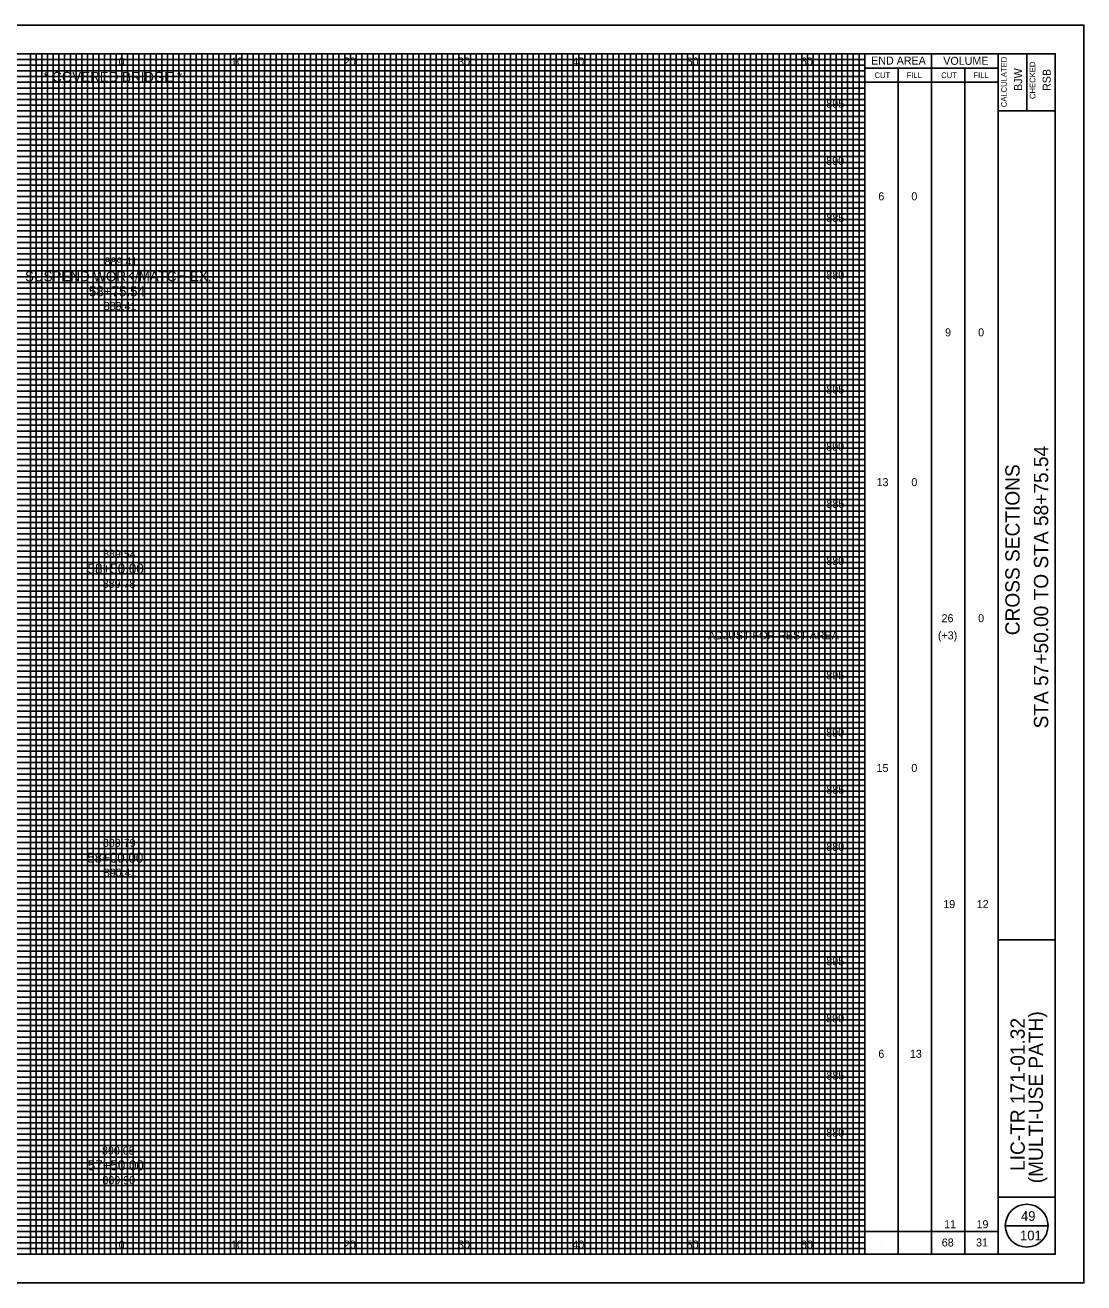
# Model space of a CAD drawing. Extents: x -10 to 160, y -2 to 2522.
# Drawn here: x 67.4 to 160, y 2412.5 to 2522.5 of the extents above; entities that cross this region are included whole.
import ezdxf

# ---------------------------------------------------------------- set-up
doc = ezdxf.new("R2010")
doc.units = 0
for name, color, linetype in [('GK_Cells', 7, 'Continuous'), ('GK_Patterns', 7, 'Continuous'), ('TX_P_10', 7, 'Continuous'), ('TX_X_10', 7, 'Continuous'), ('XS_P_Finished_Grade_Seeded', 7, 'Continuous'), ('XS_P_Pavt_Surface', 7, 'Continuous'), ('XS_P_Subgrade', 7, 'Continuous'), ('XS_X_Ground_Line', 7, 'Continuous')]:
    doc.layers.add(name, color=color, linetype=linetype)

msp = doc.modelspace()

# ---------------------------------------------------------------- linework, layer by layer
at = {"layer": 'GK_Cells'}
msp.add_lwpolyline([(-10, 2412.5), (160, 2412.5), (160, 2522.5), (-10, 2522.5)], close=True, dxfattribs=at)
at = {"layer": 'TX_P_10'}
for p, q in [((140.83, 2415), (140.83, 2520)), ((146.67, 2415), (146.67, 2520)), ((140.83, 2518.75), (152.5, 2518.75)), ((143.75, 2415), (143.75, 2518.75)), ((149.58, 2415), (149.58, 2518.75)), ((140.83, 2517.5), (152.5, 2517.5)), ((140.83, 2417), (152.5, 2417)), ((153.12, 2417.5), (156.88, 2417.5)), ((142.29, 2416), (142.29, 2416)), ((145.21, 2416), (145.21, 2416)), ((148.12, 2416), (148.12, 2416)), ((151.04, 2416), (151.04, 2416))]:
    msp.add_line(p, q, dxfattribs=at)
msp.add_circle((155, 2417.5), 1.87, dxfattribs=at)
at = {"layer": 'TX_X_10'}
for p, q in [((70.83, 2415), (70.83, 2520)), ((75.83, 2415), (75.83, 2520)), ((80.83, 2415), (80.83, 2520)), ((85.83, 2415), (85.83, 2520)), ((90.83, 2415), (90.83, 2520)), ((95.83, 2415), (95.83, 2520)), ((100.83, 2415), (100.83, 2520)), ((105.83, 2415), (105.83, 2520)), ((110.83, 2415), (110.83, 2520)), ((115.83, 2415), (115.83, 2520)), ((120.83, 2415), (120.83, 2520)), ((125.83, 2415), (125.83, 2520)), ((130.83, 2415), (130.83, 2520)), ((135.83, 2415), (135.83, 2520)), ((5.83, 2515), (140.83, 2515)), ((5.83, 2510), (140.83, 2510)), ((5.83, 2505), (140.83, 2505)), ((5.83, 2500), (140.83, 2500)), ((5.83, 2495), (140.83, 2495)), ((5.83, 2490), (140.83, 2490)), ((5.83, 2485), (140.83, 2485)), ((5.83, 2480), (140.83, 2480)), ((5.83, 2475), (140.83, 2475)), ((5.83, 2470), (140.83, 2470)), ((5.83, 2465), (140.83, 2465)), ((5.83, 2460), (140.83, 2460)), ((5.83, 2455), (140.83, 2455)), ((5.83, 2450), (140.83, 2450)), ((5.83, 2445), (140.83, 2445)), ((5.83, 2440), (140.83, 2440)), ((5.83, 2435), (140.83, 2435)), ((5.83, 2430), (140.83, 2430)), ((5.83, 2425), (140.83, 2425)), ((5.83, 2420), (140.83, 2420))]:
    msp.add_line(p, q, dxfattribs=at)
at = {"layer": 'XS_P_Pavt_Surface'}
for p, q in [((152.5, 2415), (152.5, 2520)), ((155, 2520), (155, 2515)), ((152.5, 2515), (157.5, 2515)), ((152.5, 2442.5), (157.5, 2442.5)), ((152.5, 2420), (157.5, 2420))]:
    msp.add_line(p, q, dxfattribs=at)
msp.add_lwpolyline([(0, 2520), (157.5, 2520), (157.5, 2415), (0, 2415)], close=True, dxfattribs=at)
at = {"layer": 'XS_X_Ground_Line'}
for p, q in [((5.83, 2519.5), (140.83, 2519.5)), ((5.83, 2519), (140.83, 2519)), ((67.83, 2415), (67.83, 2520)), ((68.33, 2415), (68.33, 2520)), ((68.83, 2415), (68.83, 2520)), ((69.33, 2415), (69.33, 2520)), ((69.83, 2415), (69.83, 2520)), ((70.33, 2415), (70.33, 2520)), ((71.33, 2415), (71.33, 2520)), ((71.83, 2415), (71.83, 2520)), ((72.33, 2415), (72.33, 2520)), ((72.83, 2415), (72.83, 2520)), ((73.33, 2415), (73.33, 2520)), ((73.83, 2415), (73.83, 2520)), ((74.33, 2415), (74.33, 2520)), ((74.83, 2415), (74.83, 2520)), ((75.33, 2415), (75.33, 2520)), ((76.33, 2415), (76.33, 2520)), ((76.83, 2415), (76.83, 2520)), ((77.33, 2415), (77.33, 2520)), ((77.83, 2415), (77.83, 2520)), ((78.33, 2415), (78.33, 2520)), ((78.83, 2415), (78.83, 2520)), ((79.33, 2415), (79.33, 2520)), ((79.83, 2415), (79.83, 2520)), ((80.33, 2415), (80.33, 2520)), ((81.33, 2415), (81.33, 2520)), ((81.83, 2415), (81.83, 2520)), ((82.33, 2415), (82.33, 2520)), ((82.83, 2415), (82.83, 2520)), ((83.33, 2415), (83.33, 2520)), ((83.83, 2415), (83.83, 2520)), ((84.33, 2415), (84.33, 2520)), ((84.83, 2415), (84.83, 2520)), ((85.33, 2415), (85.33, 2520)), ((86.33, 2415), (86.33, 2520)), ((86.83, 2415), (86.83, 2520)), ((87.33, 2415), (87.33, 2520)), ((87.83, 2415), (87.83, 2520)), ((88.33, 2415), (88.33, 2520)), ((88.83, 2415), (88.83, 2520)), ((89.33, 2415), (89.33, 2520)), ((89.83, 2415), (89.83, 2520)), ((90.33, 2415), (90.33, 2520)), ((91.33, 2415), (91.33, 2520)), ((91.83, 2415), (91.83, 2520)), ((92.33, 2415), (92.33, 2520)), ((92.83, 2415), (92.83, 2520)), ((93.33, 2415), (93.33, 2520)), ((93.83, 2415), (93.83, 2520)), ((94.33, 2415), (94.33, 2520)), ((94.83, 2415), (94.83, 2520)), ((95.33, 2415), (95.33, 2520)), ((96.33, 2415), (96.33, 2520)), ((96.83, 2415), (96.83, 2520)), ((97.33, 2415), (97.33, 2520)), ((97.83, 2415), (97.83, 2520)), ((98.33, 2415), (98.33, 2520)), ((98.83, 2415), (98.83, 2520)), ((99.33, 2415), (99.33, 2520)), ((99.83, 2415), (99.83, 2520)), ((100.33, 2415), (100.33, 2520)), ((101.33, 2415), (101.33, 2520)), ((101.83, 2415), (101.83, 2520)), ((102.33, 2415), (102.33, 2520)), ((102.83, 2415), (102.83, 2520)), ((103.33, 2415), (103.33, 2520)), ((103.83, 2415), (103.83, 2520)), ((104.33, 2415), (104.33, 2520)), ((104.83, 2415), (104.83, 2520)), ((105.33, 2415), (105.33, 2520)), ((106.33, 2415), (106.33, 2520)), ((106.83, 2415), (106.83, 2520)), ((107.33, 2415), (107.33, 2520)), ((107.83, 2415), (107.83, 2520)), ((108.33, 2415), (108.33, 2520)), ((108.83, 2415), (108.83, 2520)), ((109.33, 2415), (109.33, 2520)), ((109.83, 2415), (109.83, 2520)), ((110.33, 2415), (110.33, 2520)), ((111.33, 2415), (111.33, 2520)), ((111.83, 2415), (111.83, 2520)), ((112.33, 2415), (112.33, 2520)), ((112.83, 2415), (112.83, 2520)), ((113.33, 2415), (113.33, 2520)), ((113.83, 2415), (113.83, 2520)), ((114.33, 2415), (114.33, 2520)), ((114.83, 2415), (114.83, 2520)), ((115.33, 2415), (115.33, 2520)), ((116.33, 2415), (116.33, 2520)), ((116.83, 2415), (116.83, 2520)), ((117.33, 2415), (117.33, 2520)), ((117.83, 2415), (117.83, 2520)), ((118.33, 2415), (118.33, 2520)), ((118.83, 2415), (118.83, 2520)), ((119.33, 2415), (119.33, 2520)), ((119.83, 2415), (119.83, 2520)), ((120.33, 2415), (120.33, 2520)), ((121.33, 2415), (121.33, 2520)), ((121.83, 2415), (121.83, 2520)), ((122.33, 2415), (122.33, 2520)), ((122.83, 2415), (122.83, 2520)), ((123.33, 2415), (123.33, 2520)), ((123.83, 2415), (123.83, 2520)), ((124.33, 2415), (124.33, 2520)), ((124.83, 2415), (124.83, 2520)), ((125.33, 2415), (125.33, 2520)), ((126.33, 2415), (126.33, 2520)), ((126.83, 2415), (126.83, 2520)), ((127.33, 2415), (127.33, 2520)), ((127.83, 2415), (127.83, 2520)), ((128.33, 2415), (128.33, 2520)), ((128.83, 2415), (128.83, 2520)), ((129.33, 2415), (129.33, 2520)), ((129.83, 2415), (129.83, 2520)), ((130.33, 2415), (130.33, 2520)), ((131.33, 2415), (131.33, 2520)), ((131.83, 2415), (131.83, 2520)), ((132.33, 2415), (132.33, 2520)), ((132.83, 2415), (132.83, 2520)), ((133.33, 2415), (133.33, 2520)), ((133.83, 2415), (133.83, 2520)), ((134.33, 2415), (134.33, 2520)), ((134.83, 2415), (134.83, 2520)), ((135.33, 2415), (135.33, 2520)), ((136.33, 2415), (136.33, 2520)), ((136.83, 2415), (136.83, 2520)), ((137.33, 2415), (137.33, 2520)), ((137.83, 2415), (137.83, 2520)), ((138.33, 2415), (138.33, 2520)), ((138.83, 2415), (138.83, 2520)), ((139.33, 2415), (139.33, 2520)), ((139.83, 2415), (139.83, 2520)), ((140.33, 2415), (140.33, 2520)), ((5.83, 2518.5), (140.83, 2518.5)), ((5.83, 2518), (140.83, 2518)), ((5.83, 2517.5), (140.83, 2517.5)), ((5.83, 2517), (140.83, 2517)), ((5.83, 2516.5), (140.83, 2516.5)), ((5.83, 2516), (140.83, 2516)), ((5.83, 2515.5), (140.83, 2515.5)), ((5.83, 2514.5), (140.83, 2514.5)), ((5.83, 2514), (140.83, 2514)), ((5.83, 2513.5), (140.83, 2513.5)), ((5.83, 2513), (140.83, 2513)), ((5.83, 2512.5), (140.83, 2512.5)), ((5.83, 2512), (140.83, 2512)), ((5.83, 2511.5), (140.83, 2511.5)), ((5.83, 2511), (140.83, 2511)), ((5.83, 2510.5), (140.83, 2510.5)), ((5.83, 2509.5), (140.83, 2509.5)), ((5.83, 2509), (140.83, 2509)), ((5.83, 2508.5), (140.83, 2508.5)), ((5.83, 2508), (140.83, 2508)), ((5.83, 2507.5), (140.83, 2507.5)), ((5.83, 2507), (140.83, 2507)), ((5.83, 2506.5), (140.83, 2506.5)), ((5.83, 2506), (140.83, 2506)), ((5.83, 2505.5), (140.83, 2505.5)), ((5.83, 2504.5), (140.83, 2504.5)), ((5.83, 2504), (140.83, 2504)), ((5.83, 2503.5), (140.83, 2503.5)), ((5.83, 2503), (140.83, 2503)), ((5.83, 2502.5), (140.83, 2502.5)), ((5.83, 2502), (140.83, 2502)), ((5.83, 2501.5), (140.83, 2501.5)), ((5.83, 2501), (140.83, 2501)), ((5.83, 2500.5), (140.83, 2500.5)), ((5.83, 2499.5), (140.83, 2499.5)), ((5.83, 2499), (140.83, 2499)), ((5.83, 2498.5), (140.83, 2498.5)), ((5.83, 2498), (140.83, 2498)), ((5.83, 2497.5), (140.83, 2497.5)), ((5.83, 2497), (140.83, 2497)), ((5.83, 2496.5), (140.83, 2496.5)), ((5.83, 2496), (140.83, 2496)), ((5.83, 2495.5), (140.83, 2495.5)), ((5.83, 2494.5), (140.83, 2494.5)), ((5.83, 2494), (140.83, 2494)), ((5.83, 2493.5), (140.83, 2493.5)), ((5.83, 2493), (140.83, 2493)), ((5.83, 2492.5), (140.83, 2492.5)), ((5.83, 2492), (140.83, 2492)), ((5.83, 2491.5), (140.83, 2491.5)), ((5.83, 2491), (140.83, 2491)), ((5.83, 2490.5), (140.83, 2490.5)), ((5.83, 2489.5), (140.83, 2489.5)), ((5.83, 2489), (140.83, 2489)), ((5.83, 2488.5), (140.83, 2488.5)), ((5.83, 2488), (140.83, 2488)), ((5.83, 2487.5), (140.83, 2487.5)), ((5.83, 2487), (140.83, 2487)), ((5.83, 2486.5), (140.83, 2486.5)), ((5.83, 2486), (140.83, 2486)), ((5.83, 2485.5), (140.83, 2485.5)), ((5.83, 2484.5), (140.83, 2484.5)), ((5.83, 2484), (140.83, 2484)), ((5.83, 2483.5), (140.83, 2483.5)), ((5.83, 2483), (140.83, 2483)), ((5.83, 2482.5), (140.83, 2482.5)), ((5.83, 2482), (140.83, 2482)), ((5.83, 2481.5), (140.83, 2481.5)), ((5.83, 2481), (140.83, 2481)), ((5.83, 2480.5), (140.83, 2480.5)), ((5.83, 2479.5), (140.83, 2479.5)), ((5.83, 2479), (140.83, 2479)), ((5.83, 2478.5), (140.83, 2478.5)), ((5.83, 2478), (140.83, 2478)), ((5.83, 2477.5), (140.83, 2477.5)), ((5.83, 2477), (140.83, 2477)), ((5.83, 2476.5), (140.83, 2476.5)), ((5.83, 2476), (140.83, 2476)), ((5.83, 2475.5), (140.83, 2475.5)), ((5.83, 2474.5), (140.83, 2474.5)), ((5.83, 2474), (140.83, 2474)), ((5.83, 2473.5), (140.83, 2473.5)), ((5.83, 2473), (140.83, 2473)), ((5.83, 2472.5), (140.83, 2472.5)), ((5.83, 2472), (140.83, 2472)), ((5.83, 2471.5), (140.83, 2471.5)), ((5.83, 2471), (140.83, 2471)), ((5.83, 2470.5), (140.83, 2470.5)), ((5.83, 2469.5), (140.83, 2469.5)), ((5.83, 2469), (140.83, 2469)), ((5.83, 2468.5), (140.83, 2468.5)), ((5.83, 2468), (140.83, 2468)), ((5.83, 2467.5), (140.83, 2467.5)), ((5.83, 2467), (140.83, 2467)), ((5.83, 2466.5), (140.83, 2466.5)), ((5.83, 2466), (140.83, 2466)), ((5.83, 2465.5), (140.83, 2465.5)), ((5.83, 2464.5), (140.83, 2464.5)), ((5.83, 2464), (140.83, 2464)), ((5.83, 2463.5), (140.83, 2463.5)), ((5.83, 2463), (140.83, 2463)), ((5.83, 2462.5), (140.83, 2462.5)), ((5.83, 2462), (140.83, 2462)), ((5.83, 2461.5), (140.83, 2461.5)), ((5.83, 2461), (140.83, 2461)), ((5.83, 2460.5), (140.83, 2460.5)), ((5.83, 2459.5), (140.83, 2459.5)), ((5.83, 2459), (140.83, 2459)), ((5.83, 2458.5), (140.83, 2458.5)), ((5.83, 2458), (140.83, 2458)), ((5.83, 2457.5), (140.83, 2457.5)), ((5.83, 2457), (140.83, 2457)), ((5.83, 2456.5), (140.83, 2456.5)), ((5.83, 2456), (140.83, 2456)), ((5.83, 2455.5), (140.83, 2455.5)), ((5.83, 2454.5), (140.83, 2454.5)), ((5.83, 2454), (140.83, 2454)), ((5.83, 2453.5), (140.83, 2453.5)), ((5.83, 2453), (140.83, 2453)), ((5.83, 2452.5), (140.83, 2452.5)), ((5.83, 2452), (140.83, 2452)), ((5.83, 2451.5), (140.83, 2451.5)), ((5.83, 2451), (140.83, 2451)), ((5.83, 2450.5), (140.83, 2450.5)), ((5.83, 2449.5), (140.83, 2449.5)), ((5.83, 2449), (140.83, 2449)), ((5.83, 2448.5), (140.83, 2448.5)), ((5.83, 2448), (140.83, 2448)), ((5.83, 2447.5), (140.83, 2447.5)), ((5.83, 2447), (140.83, 2447)), ((5.83, 2446.5), (140.83, 2446.5)), ((5.83, 2446), (140.83, 2446)), ((5.83, 2445.5), (140.83, 2445.5)), ((5.83, 2444.5), (140.83, 2444.5)), ((5.83, 2444), (140.83, 2444)), ((5.83, 2443.5), (140.83, 2443.5)), ((5.83, 2443), (140.83, 2443)), ((5.83, 2442.5), (140.83, 2442.5)), ((5.83, 2442), (140.83, 2442)), ((5.83, 2441.5), (140.83, 2441.5)), ((5.83, 2441), (140.83, 2441)), ((5.83, 2440.5), (140.83, 2440.5)), ((5.83, 2439.5), (140.83, 2439.5)), ((5.83, 2439), (140.83, 2439)), ((5.83, 2438.5), (140.83, 2438.5)), ((5.83, 2438), (140.83, 2438)), ((5.83, 2437.5), (140.83, 2437.5)), ((5.83, 2437), (140.83, 2437)), ((5.83, 2436.5), (140.83, 2436.5)), ((5.83, 2436), (140.83, 2436)), ((5.83, 2435.5), (140.83, 2435.5)), ((5.83, 2434.5), (140.83, 2434.5)), ((5.83, 2434), (140.83, 2434)), ((5.83, 2433.5), (140.83, 2433.5)), ((5.83, 2433), (140.83, 2433)), ((5.83, 2432.5), (140.83, 2432.5)), ((5.83, 2432), (140.83, 2432)), ((5.83, 2431.5), (140.83, 2431.5)), ((5.83, 2431), (140.83, 2431)), ((5.83, 2430.5), (140.83, 2430.5)), ((5.83, 2429.5), (140.83, 2429.5)), ((5.83, 2429), (140.83, 2429)), ((5.83, 2428.5), (140.83, 2428.5)), ((5.83, 2428), (140.83, 2428)), ((5.83, 2427.5), (140.83, 2427.5)), ((5.83, 2427), (140.83, 2427)), ((5.83, 2426.5), (140.83, 2426.5)), ((5.83, 2426), (140.83, 2426)), ((5.83, 2425.5), (140.83, 2425.5)), ((5.83, 2424.5), (140.83, 2424.5)), ((5.83, 2424), (140.83, 2424)), ((5.83, 2423.5), (140.83, 2423.5)), ((5.83, 2423), (140.83, 2423)), ((5.83, 2422.5), (140.83, 2422.5)), ((5.83, 2422), (140.83, 2422)), ((5.83, 2421.5), (140.83, 2421.5)), ((5.83, 2421), (140.83, 2421)), ((5.83, 2420.5), (140.83, 2420.5)), ((5.83, 2419.5), (140.83, 2419.5)), ((5.83, 2419), (140.83, 2419)), ((5.83, 2418.5), (140.83, 2418.5)), ((5.83, 2418), (140.83, 2418)), ((5.83, 2417.5), (140.83, 2417.5)), ((5.83, 2417), (140.83, 2417)), ((5.83, 2416.5), (140.83, 2416.5)), ((5.83, 2416), (140.83, 2416)), ((5.83, 2415.5), (140.83, 2415.5))]:
    msp.add_line(p, q, dxfattribs=at)

# ---------------------------------------------------------------- texts
at = {"layer": 'GK_Patterns'}
for s, height, p in [('0', 0.7, (75.55, 2518.97)), ('0', 0.7, (75.55, 2518.97)), ('10', 0.7, (85.39, 2518.97)), ('20', 0.7, (95.26, 2518.97)), ('30', 0.7, (105.25, 2518.97)), ('40', 0.7, (115.25, 2518.97)), ('50', 0.7, (125.25, 2518.97)), ('60', 0.7, (135.25, 2518.97)), ('* COVERED BRIDGE *', 0.875, (68.96, 2517.54)), ('895', 0.7, (137.47, 2515.28)), ('890', 0.7, (137.46, 2510.28)), ('6', 0.7, (142.02, 2507.18)), ('0', 0.7, (144.91, 2507.18)), ('885', 0.7, (137.48, 2505.28)), ('SUSPEND WORK/MATCH EX.', 0.875, (67.36, 2500.1)), ('880', 0.7, (137.47, 2500.28)), ('58+75.54', 0.875, (72.95, 2498.79)), ('9', 0.7, (147.86, 2495.28)), ('0', 0.7, (150.75, 2495.28)), ('895', 0.7, (137.47, 2490.28)), ('890', 0.7, (137.46, 2485.28)), ('13', 0.7, (141.87, 2482.18)), ('0', 0.7, (144.91, 2482.18)), ('885', 0.7, (137.48, 2480.28)), ('58+50.00', 0.875, (72.84, 2474.53)), ('880', 0.7, (137.47, 2475.28)), ('26', 0.7, (147.55, 2470.28)), ('0', 0.7, (150.75, 2470.28)), ('(+3)', 0.7, (147.23, 2468.78)), ('ADJUST FOR REST AREA', 0.7, (127.12, 2468.78)), ('895', 0.7, (137.47, 2465.28)), ('890', 0.7, (137.46, 2460.28)), ('15', 0.7, (141.86, 2457.18)), ('0', 0.7, (144.91, 2457.18)), ('885', 0.7, (137.48, 2455.28)), ('880', 0.7, (137.47, 2450.28)), ('58+00.00', 0.875, (72.8, 2449.25)), ('19', 0.7, (147.7, 2445.28)), ('12', 0.7, (150.63, 2445.28)), ('895', 0.7, (137.47, 2440.28)), ('890', 0.7, (137.46, 2435.28)), ('6', 0.7, (142.02, 2432.18)), ('13', 0.7, (144.78, 2432.18)), ('885', 0.7, (137.48, 2430.28)), ('880', 0.7, (137.47, 2425.28)), ('57+50.00', 0.875, (72.85, 2422.34)), ('11', 0.7, (147.78, 2417.28)), ('19', 0.7, (150.61, 2417.28)), ('0', 0.7, (75.55, 2415.5)), ('0', 0.7, (75.55, 2415.5)), ('10', 0.7, (85.39, 2415.5)), ('20', 0.7, (95.26, 2415.5)), ('30', 0.7, (105.25, 2415.5)), ('40', 0.7, (115.25, 2415.5)), ('50', 0.7, (125.25, 2415.5)), ('60', 0.7, (135.25, 2415.5)), ('68', 0.7, (147.57, 2415.68)), ('31', 0.7, (150.57, 2415.68))]:
    msp.add_text(s, height=height, dxfattribs=at).set_placement(p)
at = {"layer": 'TX_P_10'}
for s, height, p in [('END AREA', 0.7, (141.39, 2519.05)), ('VOLUME', 0.7, (147.7, 2519.03)), ('CUT', 0.5, (141.68, 2517.87)), ('FILL', 0.5, (144.5, 2517.87)), ('CUT', 0.5, (147.52, 2517.87)), ('FILL', 0.5, (150.34, 2517.87)), ('49', 0.85, (154.5, 2417.92)), ('101', 0.85, (154.42, 2416.22))]:
    msp.add_text(s, height=height, dxfattribs=at).set_placement(p)
for s, height, p in [('CALCULATED', 0.5, (153.26, 2515.32)), ('CHECKED', 0.5, (155.76, 2516.04)), ('BJW', 0.7, (154.6, 2516.75)), ('RSB', 0.7, (157.1, 2516.75)), ('STA 57+50.00 TO STA 58+75.54', 1.25, (156.88, 2460.99)), ('CROSS SECTIONS', 1.25, (154.38, 2469.14)), ('LIC-TR 171-01.32', 1.25, (154.83, 2422.29)), ('(MULTI-USE PATH)', 1.25, (156.42, 2421.21))]:
    msp.add_text(s, height=height, rotation=90, dxfattribs=at).set_placement(p)
at = {"layer": 'XS_P_Finished_Grade_Seeded'}
for s, p in [('889.41', (74.25, 2497.58)), ('889.78', (74.15, 2473.29)), ('890.41', (74.25, 2448.03)), ('889.90', (74.13, 2421.13))]:
    msp.add_text(s, height=0.7, dxfattribs=at).set_placement(p)
at = {"layer": 'XS_P_Subgrade'}
for s, p in [('889.41', (74.32, 2501.48)), ('889.54', (74.19, 2475.91)), ('889.79', (74.17, 2450.63)), ('890.05', (74.1, 2423.72))]:
    msp.add_text(s, height=0.7, dxfattribs=at).set_placement(p)

doc.saveas('drawing.dxf')
